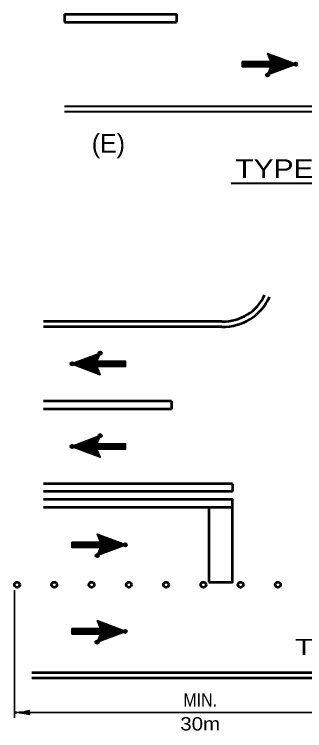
# Model space of a CAD drawing. Extents: x -96 to 617, y -65 to 388.
# Drawn here: x 326.3 to 380.8, y 106.9 to 241.5 of the extents above; entities that cross this region are included whole.
import ezdxf
from ezdxf.enums import TextEntityAlignment as Align

# ---------------------------------------------------------------- set-up
doc = ezdxf.new("R2010")
doc.units = 0
doc.header["$PDMODE"] = 32
doc.header["$PDSIZE"] = 0.5
doc.layers.add('1', color=7, linetype='Continuous', lineweight=53)

msp = doc.modelspace()

# ---------------------------------------------------------------- linework, layer by layer
at = {"layer": '1'}
for p, q in [((335.757, 241.515), (335.757, 240.015)), ((335.757, 241.515), (356.757, 241.515)), ((356.757, 241.515), (356.757, 240.015)), ((335.757, 240.015), (356.757, 240.015)), ((365.315, 183.817), (331.815, 183.817)), ((365.315, 182.817), (331.815, 182.817)), ((355.815, 168.817), (331.815, 168.817)), ((355.815, 168.817), (355.815, 167.317)), ((355.815, 167.317), (331.815, 167.317)), ((367.315, 153.317), (331.815, 153.317)), ((367.315, 153.317), (367.315, 151.817)), ((367.315, 151.817), (331.815, 151.817)), ((367.315, 148.817), (331.815, 148.817)), ((362.815, 148.817), (362.815, 134.817)), ((329.565, 117.817), (472.565, 117.817)), ((329.565, 116.817), (472.565, 116.817))]:
    msp.add_line(p, q, dxfattribs=at)
at = {"layer": '1', "lineweight": 35}
for p, q in [((373.891, 234.063), (376.827, 231.228)), ((373.992, 233.861), (376.726, 231.127)), ((374.093, 234.063), (376.928, 231.228)), ((374.093, 233.658), (376.625, 231.127)), ((374.195, 233.355), (376.523, 231.127)), ((374.296, 233.962), (377.03, 231.33)), ((374.296, 233.152), (376.422, 231.026)), ((374.397, 232.95), (376.321, 231.026)), ((374.498, 233.962), (377.131, 231.33)), ((374.802, 233.861), (377.232, 231.33)), ((375.005, 233.76), (377.333, 231.431)), ((375.207, 233.658), (377.435, 231.431)), ((375.41, 233.557), (377.536, 231.532)), ((375.713, 233.456), (377.637, 231.532)), ((375.916, 233.355), (377.738, 231.532)), ((376.118, 233.355), (377.84, 231.633)), ((376.422, 233.253), (377.941, 231.633)), ((376.625, 233.152), (378.042, 231.735)), ((376.827, 233.051), (378.143, 231.735)), ((377.03, 232.95), (378.245, 231.735)), ((369.132, 232.646), (374.498, 232.646)), ((369.132, 232.545), (370.043, 231.633)), ((369.132, 232.443), (369.942, 231.633)), ((369.132, 232.342), (369.841, 231.633)), ((369.132, 232.14), (369.638, 231.633)), ((369.132, 232.038), (369.537, 231.633)), ((369.132, 231.836), (369.335, 231.633)), ((369.132, 231.735), (369.233, 231.633)), ((369.233, 232.646), (370.246, 231.633)), ((369.335, 232.646), (370.347, 231.633)), ((369.537, 232.646), (370.55, 231.633)), ((369.638, 232.646), (370.651, 231.633)), ((369.841, 232.646), (370.853, 231.633)), ((369.942, 232.646), (370.955, 231.633)), ((370.043, 232.646), (371.056, 231.633)), ((370.246, 232.646), (371.258, 231.633)), ((370.347, 232.646), (371.36, 231.633)), ((370.55, 232.646), (371.562, 231.633)), ((370.651, 232.646), (371.663, 231.633)), ((370.752, 232.646), (371.765, 231.633)), ((370.955, 232.646), (371.967, 231.633)), ((371.056, 232.646), (372.068, 231.633)), ((371.258, 232.646), (372.271, 231.633)), ((371.36, 232.646), (372.372, 231.633)), ((371.562, 232.646), (372.575, 231.633)), ((371.663, 232.646), (372.676, 231.633)), ((371.765, 232.646), (372.777, 231.633)), ((371.967, 232.646), (372.98, 231.633)), ((372.068, 232.646), (373.081, 231.633)), ((372.271, 232.646), (373.283, 231.633)), ((372.372, 232.646), (373.385, 231.633)), ((372.473, 232.646), (373.486, 231.633)), ((372.676, 232.646), (373.688, 231.633)), ((372.777, 232.646), (373.79, 231.633)), ((372.98, 232.646), (373.992, 231.633)), ((373.081, 232.646), (374.093, 231.633)), ((373.182, 232.646), (374.195, 231.633)), ((373.385, 232.646), (374.397, 231.633)), ((373.486, 232.646), (375.41, 230.722)), ((373.688, 232.646), (375.612, 230.722)), ((373.79, 232.646), (375.713, 230.823)), ((373.992, 232.646), (375.815, 230.823)), ((374.093, 232.646), (375.916, 230.823)), ((374.195, 232.646), (376.017, 230.925)), ((374.397, 232.646), (376.118, 230.925)), ((374.498, 232.646), (376.22, 231.026)), ((377.333, 232.848), (378.346, 231.836)), ((377.536, 232.747), (378.447, 231.836)), ((377.738, 232.747), (378.548, 231.836)), ((377.941, 232.646), (378.65, 231.937)), ((378.245, 232.545), (378.751, 231.937)), ((378.447, 232.443), (378.852, 232.038)), ((378.65, 232.342), (378.953, 232.038)), ((378.852, 232.241), (379.055, 232.038)), ((373.891, 230.216), (373.992, 230.115)), ((373.992, 230.418), (374.195, 230.216)), ((373.992, 230.317), (374.093, 230.216)), ((374.093, 230.722), (374.498, 230.317)), ((374.093, 230.621), (374.397, 230.317)), ((374.093, 230.52), (374.296, 230.317)), ((374.195, 230.925), (374.701, 230.418)), ((374.195, 230.823), (374.6, 230.418)), ((374.296, 231.228), (375.005, 230.52)), ((374.296, 231.127), (374.903, 230.52)), ((374.296, 231.026), (374.802, 230.52)), ((374.397, 231.431), (375.207, 230.621)), ((374.397, 231.33), (375.106, 230.621)), ((374.498, 231.532), (375.308, 230.621)), ((342.339, 177.539), (342.136, 177.741)), ((342.339, 177.64), (342.238, 177.741)), ((342.44, 177.741), (342.339, 177.842)), ((340.415, 174.602), (338.592, 176.425)), ((340.618, 174.501), (338.694, 176.425)), ((340.921, 174.4), (338.795, 176.425)), ((341.124, 174.299), (338.896, 176.526)), ((341.326, 174.197), (338.998, 176.526)), ((341.529, 174.096), (339.099, 176.627)), ((341.832, 173.995), (339.2, 176.627)), ((342.035, 173.995), (339.301, 176.627)), ((342.238, 173.894), (339.402, 176.729)), ((342.44, 173.894), (339.504, 176.729)), ((342.339, 174.096), (339.605, 176.83)), ((342.238, 174.299), (339.706, 176.83)), ((342.136, 174.602), (339.808, 176.83)), ((342.035, 174.805), (339.909, 176.931)), ((341.934, 175.007), (340.01, 176.931)), ((341.832, 175.311), (340.111, 176.931)), ((341.934, 175.311), (340.212, 177.032)), ((342.136, 175.311), (340.314, 177.032)), ((342.238, 175.311), (340.415, 177.134)), ((342.339, 175.311), (340.516, 177.134)), ((342.541, 175.311), (340.618, 177.134)), ((342.642, 175.311), (340.719, 177.235)), ((342.845, 175.311), (340.921, 177.235)), ((341.832, 176.425), (341.022, 177.336)), ((341.934, 176.526), (341.124, 177.336)), ((341.934, 176.627), (341.225, 177.336)), ((342.035, 176.729), (341.326, 177.437)), ((342.035, 176.83), (341.428, 177.437)), ((342.035, 176.931), (341.529, 177.437)), ((342.136, 177.032), (341.63, 177.539)), ((342.136, 177.134), (341.731, 177.539)), ((342.238, 177.235), (341.832, 177.64)), ((342.238, 177.336), (341.934, 177.64)), ((342.238, 177.437), (342.035, 177.64)), ((337.479, 175.716), (337.276, 175.919)), ((337.681, 175.615), (337.377, 175.919)), ((337.884, 175.514), (337.479, 175.919)), ((338.086, 175.412), (337.58, 176.02)), ((338.39, 175.311), (337.681, 176.02)), ((338.592, 175.21), (337.782, 176.121)), ((338.795, 175.21), (337.884, 176.121)), ((338.998, 175.109), (337.985, 176.121)), ((339.301, 175.007), (338.086, 176.222)), ((339.504, 174.906), (338.188, 176.222)), ((339.706, 174.805), (338.289, 176.222)), ((339.909, 174.704), (338.39, 176.324)), ((340.212, 174.602), (338.491, 176.324)), ((347.199, 175.311), (341.832, 175.311)), ((342.946, 175.311), (341.934, 176.324)), ((343.149, 175.311), (342.136, 176.324)), ((343.25, 175.311), (342.238, 176.324)), ((343.351, 175.311), (342.339, 176.324)), ((343.554, 175.311), (342.541, 176.324)), ((343.655, 175.311), (342.642, 176.324)), ((343.858, 175.311), (342.845, 176.324)), ((343.959, 175.311), (342.946, 176.324)), ((344.06, 175.311), (343.048, 176.324)), ((344.262, 175.311), (343.25, 176.324)), ((344.364, 175.311), (343.351, 176.324)), ((344.566, 175.311), (343.554, 176.324)), ((344.667, 175.311), (343.655, 176.324)), ((344.769, 175.311), (343.756, 176.324)), ((344.971, 175.311), (343.959, 176.324)), ((345.072, 175.311), (344.06, 176.324)), ((345.275, 175.311), (344.262, 176.324)), ((345.376, 175.311), (344.364, 176.324)), ((345.579, 175.311), (344.566, 176.324)), ((345.68, 175.311), (344.667, 176.324)), ((345.781, 175.311), (344.769, 176.324)), ((345.984, 175.311), (344.971, 176.324)), ((346.085, 175.311), (345.072, 176.324)), ((346.287, 175.311), (345.275, 176.324)), ((346.389, 175.311), (345.376, 176.324)), ((346.49, 175.311), (345.477, 176.324)), ((346.692, 175.311), (345.68, 176.324)), ((346.794, 175.311), (345.781, 176.324)), ((346.996, 175.311), (345.984, 176.324)), ((347.097, 175.311), (346.085, 176.324)), ((347.199, 175.412), (346.287, 176.324)), ((347.199, 175.514), (346.389, 176.324)), ((347.199, 175.615), (346.49, 176.324)), ((347.199, 175.817), (346.692, 176.324)), ((347.199, 175.919), (346.794, 176.324)), ((347.199, 176.121), (346.996, 176.324)), ((347.199, 176.222), (347.097, 176.324)), ((342.238, 159.811), (340.415, 161.634)), ((342.339, 159.811), (340.516, 161.634)), ((342.541, 159.811), (340.618, 161.634)), ((342.642, 159.811), (340.719, 161.735)), ((342.845, 159.811), (340.921, 161.735)), ((341.832, 160.925), (341.022, 161.836)), ((341.934, 161.026), (341.124, 161.836)), ((341.934, 161.127), (341.225, 161.836)), ((342.035, 161.229), (341.326, 161.937)), ((342.035, 161.33), (341.428, 161.937)), ((342.035, 161.431), (341.529, 161.937)), ((342.136, 161.532), (341.63, 162.039)), ((342.136, 161.634), (341.731, 162.039)), ((342.238, 161.735), (341.832, 162.14)), ((342.238, 161.836), (341.934, 162.14)), ((342.238, 161.937), (342.035, 162.14)), ((342.339, 162.039), (342.136, 162.241)), ((342.339, 162.14), (342.238, 162.241)), ((342.44, 162.241), (342.339, 162.342)), ((337.479, 160.216), (337.276, 160.419)), ((337.681, 160.115), (337.377, 160.419)), ((337.884, 160.014), (337.479, 160.419)), ((338.086, 159.912), (337.58, 160.52)), ((338.39, 159.811), (337.681, 160.52)), ((338.592, 159.71), (337.782, 160.621)), ((338.795, 159.71), (337.884, 160.621)), ((338.998, 159.609), (337.985, 160.621)), ((339.301, 159.507), (338.086, 160.722)), ((339.504, 159.406), (338.188, 160.722)), ((339.706, 159.305), (338.289, 160.722)), ((339.909, 159.204), (338.39, 160.824)), ((340.212, 159.102), (338.491, 160.824)), ((340.415, 159.102), (338.592, 160.925)), ((340.618, 159.001), (338.694, 160.925)), ((340.921, 158.9), (338.795, 160.925)), ((341.124, 158.799), (338.896, 161.026)), ((341.326, 158.697), (338.998, 161.026)), ((341.529, 158.596), (339.099, 161.127)), ((341.832, 158.495), (339.2, 161.127)), ((342.035, 158.495), (339.301, 161.127)), ((342.238, 158.394), (339.402, 161.229)), ((342.44, 158.394), (339.504, 161.229)), ((342.339, 158.596), (339.605, 161.33)), ((342.238, 158.799), (339.706, 161.33)), ((342.136, 159.102), (339.808, 161.33)), ((342.035, 159.305), (339.909, 161.431)), ((341.934, 159.507), (340.01, 161.431)), ((341.832, 159.811), (340.111, 161.431)), ((341.934, 159.811), (340.212, 161.532)), ((342.136, 159.811), (340.314, 161.532)), ((342.946, 159.811), (341.934, 160.824)), ((343.149, 159.811), (342.136, 160.824)), ((343.25, 159.811), (342.238, 160.824)), ((343.351, 159.811), (342.339, 160.824)), ((343.554, 159.811), (342.541, 160.824)), ((343.655, 159.811), (342.642, 160.824)), ((343.858, 159.811), (342.845, 160.824)), ((343.959, 159.811), (342.946, 160.824)), ((344.06, 159.811), (343.048, 160.824)), ((344.262, 159.811), (343.25, 160.824)), ((344.364, 159.811), (343.351, 160.824)), ((344.566, 159.811), (343.554, 160.824)), ((344.667, 159.811), (343.655, 160.824)), ((344.769, 159.811), (343.756, 160.824)), ((344.971, 159.811), (343.959, 160.824)), ((345.072, 159.811), (344.06, 160.824)), ((345.275, 159.811), (344.262, 160.824)), ((345.376, 159.811), (344.364, 160.824)), ((345.579, 159.811), (344.566, 160.824)), ((345.68, 159.811), (344.667, 160.824)), ((345.781, 159.811), (344.769, 160.824)), ((345.984, 159.811), (344.971, 160.824)), ((346.085, 159.811), (345.072, 160.824)), ((346.287, 159.811), (345.275, 160.824)), ((346.389, 159.811), (345.376, 160.824)), ((346.49, 159.811), (345.477, 160.824)), ((346.692, 159.811), (345.68, 160.824)), ((346.794, 159.811), (345.781, 160.824)), ((346.996, 159.811), (345.984, 160.824)), ((347.097, 159.811), (346.085, 160.824)), ((347.199, 159.912), (346.287, 160.824)), ((347.199, 160.014), (346.389, 160.824)), ((347.199, 160.115), (346.49, 160.824)), ((347.199, 160.317), (346.692, 160.824)), ((347.199, 160.419), (346.794, 160.824)), ((347.199, 160.621), (346.996, 160.824)), ((347.199, 160.722), (347.097, 160.824)), ((347.199, 159.811), (341.832, 159.811)), ((341.879, 143.741), (344.816, 140.906)), ((341.981, 143.539), (344.714, 140.805)), ((342.082, 143.741), (344.917, 140.906)), ((342.082, 143.336), (344.613, 140.805)), ((342.183, 143.032), (344.512, 140.805)), ((342.284, 143.64), (345.018, 141.007)), ((342.284, 142.83), (344.411, 140.704)), ((342.487, 143.64), (345.119, 141.007)), ((342.791, 143.539), (345.221, 141.007)), ((342.993, 143.437), (345.322, 141.109)), ((343.196, 143.336), (345.423, 141.109)), ((343.398, 143.235), (345.524, 141.21)), ((343.702, 143.134), (345.626, 141.21)), ((343.904, 143.032), (345.727, 141.21)), ((344.107, 143.032), (345.828, 141.311)), ((344.411, 142.931), (345.929, 141.311)), ((344.613, 142.83), (346.031, 141.412)), ((344.816, 142.729), (346.132, 141.412)), ((337.121, 142.324), (342.487, 142.324)), ((337.121, 142.222), (338.032, 141.311)), ((337.121, 142.121), (337.931, 141.311)), ((337.121, 142.02), (337.829, 141.311)), ((337.121, 141.817), (337.627, 141.311)), ((337.121, 141.716), (337.526, 141.311)), ((337.121, 141.514), (337.323, 141.311)), ((337.121, 141.412), (337.222, 141.311)), ((337.222, 142.324), (338.234, 141.311)), ((337.323, 142.324), (338.336, 141.311)), ((337.526, 142.324), (338.538, 141.311)), ((337.627, 142.324), (338.639, 141.311)), ((337.829, 142.324), (338.842, 141.311)), ((337.931, 142.324), (338.943, 141.311)), ((338.032, 142.324), (339.044, 141.311)), ((338.234, 142.324), (339.247, 141.311)), ((338.336, 142.324), (339.348, 141.311)), ((338.538, 142.324), (339.551, 141.311)), ((338.639, 142.324), (339.652, 141.311)), ((338.741, 142.324), (339.753, 141.311)), ((338.943, 142.324), (339.956, 141.311)), ((339.044, 142.324), (340.057, 141.311)), ((339.247, 142.324), (340.259, 141.311)), ((339.348, 142.324), (340.361, 141.311)), ((339.551, 142.324), (340.563, 141.311)), ((339.652, 142.324), (340.664, 141.311)), ((339.753, 142.324), (340.766, 141.311)), ((339.956, 142.324), (340.968, 141.311)), ((340.057, 142.324), (341.069, 141.311)), ((340.259, 142.324), (341.272, 141.311)), ((340.361, 142.324), (341.373, 141.311)), ((340.462, 142.324), (341.474, 141.311)), ((340.664, 142.324), (341.677, 141.311)), ((340.766, 142.324), (341.778, 141.311)), ((340.968, 142.324), (341.981, 141.311)), ((341.069, 142.324), (342.082, 141.311)), ((341.171, 142.324), (342.183, 141.311)), ((341.373, 142.324), (342.386, 141.311)), ((341.474, 142.324), (343.398, 140.4)), ((341.677, 142.324), (343.601, 140.4)), ((341.778, 142.324), (343.702, 140.501)), ((341.981, 142.324), (343.803, 140.501)), ((342.082, 142.324), (343.904, 140.501)), ((342.183, 142.324), (344.006, 140.602)), ((342.386, 142.627), (344.309, 140.704)), ((342.386, 142.324), (344.107, 140.602)), ((342.487, 142.324), (344.208, 140.704)), ((345.018, 142.627), (346.233, 141.412)), ((345.322, 142.526), (346.334, 141.514)), ((345.524, 142.425), (346.436, 141.514)), ((345.727, 142.425), (346.537, 141.514)), ((345.929, 142.324), (346.638, 141.615)), ((346.233, 142.222), (346.739, 141.615)), ((346.436, 142.121), (346.841, 141.716)), ((346.638, 142.02), (346.942, 141.716)), ((346.841, 141.919), (347.043, 141.716)), ((341.981, 140.096), (342.183, 139.894)), ((342.082, 140.4), (342.487, 139.995)), ((342.082, 140.299), (342.386, 139.995)), ((342.082, 140.197), (342.284, 139.995)), ((342.183, 140.602), (342.689, 140.096)), ((342.183, 140.501), (342.588, 140.096)), ((342.284, 140.906), (342.993, 140.197)), ((342.284, 140.805), (342.892, 140.197)), ((342.284, 140.704), (342.791, 140.197)), ((342.386, 141.109), (343.196, 140.299)), ((342.386, 141.007), (343.094, 140.299)), ((342.487, 141.21), (343.297, 140.299)), ((341.879, 139.894), (341.981, 139.792)), ((341.981, 139.995), (342.082, 139.894)), ((326.315, 133.317), (326.315, 109.317)), ((341.879, 127.491), (344.816, 124.656)), ((341.981, 127.289), (344.714, 124.555)), ((342.082, 127.491), (344.917, 124.656)), ((342.082, 127.086), (344.613, 124.555)), ((342.183, 126.782), (344.512, 124.555)), ((342.284, 127.39), (345.018, 124.757)), ((342.284, 126.58), (344.411, 124.454)), ((342.487, 127.39), (345.119, 124.757)), ((342.791, 127.289), (345.221, 124.757)), ((342.993, 127.187), (345.322, 124.859)), ((343.196, 127.086), (345.423, 124.859)), ((343.398, 126.985), (345.524, 124.96)), ((343.702, 126.884), (345.626, 124.96)), ((343.904, 126.782), (345.727, 124.96)), ((344.107, 126.782), (345.828, 125.061)), ((344.411, 126.681), (345.929, 125.061)), ((344.613, 126.58), (346.031, 125.162)), ((337.121, 126.074), (342.487, 126.074)), ((337.121, 125.972), (338.032, 125.061)), ((337.121, 125.871), (337.931, 125.061)), ((337.121, 125.77), (337.829, 125.061)), ((337.121, 125.567), (337.627, 125.061)), ((337.121, 125.466), (337.526, 125.061)), ((337.121, 125.264), (337.323, 125.061)), ((337.222, 126.074), (338.234, 125.061)), ((337.323, 126.074), (338.336, 125.061)), ((337.526, 126.074), (338.538, 125.061)), ((337.627, 126.074), (338.639, 125.061)), ((337.829, 126.074), (338.842, 125.061)), ((337.931, 126.074), (338.943, 125.061)), ((338.032, 126.074), (339.044, 125.061)), ((338.234, 126.074), (339.247, 125.061)), ((338.336, 126.074), (339.348, 125.061)), ((338.538, 126.074), (339.551, 125.061)), ((338.639, 126.074), (339.652, 125.061)), ((338.741, 126.074), (339.753, 125.061)), ((338.943, 126.074), (339.956, 125.061)), ((339.044, 126.074), (340.057, 125.061)), ((339.247, 126.074), (340.259, 125.061)), ((339.348, 126.074), (340.361, 125.061)), ((339.551, 126.074), (340.563, 125.061)), ((339.652, 126.074), (340.664, 125.061)), ((339.753, 126.074), (340.766, 125.061)), ((339.956, 126.074), (340.968, 125.061)), ((340.057, 126.074), (341.069, 125.061)), ((340.259, 126.074), (341.272, 125.061)), ((340.361, 126.074), (341.373, 125.061)), ((340.462, 126.074), (341.474, 125.061)), ((340.664, 126.074), (341.677, 125.061)), ((340.766, 126.074), (341.778, 125.061)), ((340.968, 126.074), (341.981, 125.061)), ((341.069, 126.074), (342.082, 125.061)), ((341.171, 126.074), (342.183, 125.061)), ((341.373, 126.074), (342.386, 125.061)), ((341.474, 126.074), (343.398, 124.15)), ((341.677, 126.074), (343.601, 124.15)), ((341.778, 126.074), (343.702, 124.251)), ((341.981, 126.074), (343.803, 124.251)), ((342.082, 126.074), (343.904, 124.251)), ((342.183, 126.074), (344.006, 124.352)), ((342.386, 126.377), (344.309, 124.454)), ((342.386, 126.074), (344.107, 124.352)), ((342.487, 126.074), (344.208, 124.454)), ((344.816, 126.479), (346.132, 125.162)), ((345.018, 126.377), (346.233, 125.162)), ((345.322, 126.276), (346.334, 125.264)), ((345.524, 126.175), (346.436, 125.264)), ((345.727, 126.175), (346.537, 125.264)), ((345.929, 126.074), (346.638, 125.365)), ((346.233, 125.972), (346.739, 125.365)), ((346.436, 125.871), (346.841, 125.466)), ((346.638, 125.77), (346.942, 125.466)), ((346.841, 125.669), (347.043, 125.466)), ((337.121, 125.162), (337.222, 125.061)), ((341.981, 123.846), (342.183, 123.644)), ((342.082, 124.15), (342.487, 123.745)), ((342.082, 124.049), (342.386, 123.745)), ((342.082, 123.947), (342.284, 123.745)), ((342.183, 124.352), (342.689, 123.846)), ((342.183, 124.251), (342.588, 123.846)), ((342.284, 124.656), (342.993, 123.947)), ((342.284, 124.555), (342.892, 123.947)), ((342.284, 124.454), (342.791, 123.947)), ((342.386, 124.859), (343.196, 124.049)), ((342.386, 124.757), (343.094, 124.049)), ((342.487, 124.96), (343.297, 124.049)), ((341.879, 123.644), (341.981, 123.542)), ((341.981, 123.745), (342.082, 123.644))]:
    msp.add_line(p, q, dxfattribs=at)
at = {"layer": '1', "lineweight": 40}
for p, q in [((335.757, 224.265), (446.257, 224.265)), ((335.757, 223.265), (446.257, 223.265)), ((367.007, 209.768), (424.245, 209.768))]:
    msp.add_line(p, q, dxfattribs=at)
at = {"layer": '1', "lineweight": 35}
for points in [[(379.257, 232.14), (373.891, 230.115), (374.498, 231.633), (369.132, 231.633), (369.132, 232.646), (374.498, 232.646), (373.891, 234.165)], [(337.074, 175.817), (342.44, 177.842), (341.832, 176.324), (347.199, 176.324), (347.199, 175.311), (341.832, 175.311), (342.44, 173.792)], [(337.074, 160.317), (342.44, 162.342), (341.832, 160.824), (347.199, 160.824), (347.199, 159.811), (341.832, 159.811), (342.44, 158.292)], [(347.246, 141.817), (341.879, 139.792), (342.487, 141.311), (337.121, 141.311), (337.121, 142.324), (342.487, 142.324), (341.879, 143.842)], [(347.246, 125.567), (341.879, 123.542), (342.487, 125.061), (337.121, 125.061), (337.121, 126.074), (342.487, 126.074), (341.879, 127.592)]]:
    msp.add_lwpolyline(points, close=True, dxfattribs=at)
for points in [[(374.498, 231.633), (369.132, 231.633), (369.132, 232.646)], [(341.832, 176.324), (347.199, 176.324), (347.199, 175.311)], [(341.832, 160.824), (347.199, 160.824), (347.199, 159.811)], [(342.487, 141.311), (337.121, 141.311), (337.121, 142.324)], [(342.487, 125.061), (337.121, 125.061), (337.121, 126.074)], [(326.315, 110.317), (401.065, 110.317), (474.315, 110.317)]]:
    msp.add_lwpolyline(points, dxfattribs=at)
at = {"layer": '1'}
msp.add_lwpolyline([(362.815, 134.817), (367.315, 134.817), (367.315, 150.317), (331.815, 150.317)], dxfattribs=at)
for centre in [(326.815, 134.317), (333.815, 134.317), (340.815, 134.317), (347.815, 134.317), (354.815, 134.317), (361.815, 134.317), (368.815, 134.317), (375.815, 134.317)]:
    msp.add_circle(centre, 0.5, dxfattribs=at)
for radius in [8.411, 9.411]:
    msp.add_arc((365.624, 192.223), radius, 267.89429, 336.11648, dxfattribs=at)
at = {"layer": '1', "lineweight": 40}
for centre, major_axis, ratio, start_param, end_param in [((327.406, 110.594), (-1.786, -0.156), 0.122415, 0.8963533, 3.1415927), ((327.406, 110.594), (-1.786, -0.156), 0.122415, 0.8963533, 3.1415927), ((327.435, 110.106), (-1.756, 0.176), 0.07063, 3.1407148, 5.41811), ((327.435, 110.106), (-1.756, 0.176), 0.07063, 3.1407148, 5.41811)]:
    msp.add_ellipse(centre, major_axis=major_axis, ratio=ratio, start_param=start_param, end_param=end_param, dxfattribs=at)
at = {"layer": '1'}
for p in [(379.156, 232.14), (373.891, 230.115), (342.44, 177.842), (337.175, 175.817), (342.44, 162.342), (337.175, 160.317), (347.144, 141.817), (341.879, 139.792), (347.144, 125.567), (341.879, 123.542)]:
    msp.add_point(p, dxfattribs=at)

# ---------------------------------------------------------------- texts
msp.add_text('(E)', height=3.5, dxfattribs=at).set_placement((343.969, 215.538), align=Align.CENTER)
for s, height, width, p in [('TYPE C-4 MARKERS', 3.5, 1.2, (395.137, 210.768)), ('THRU         LANE', 3, 1.4, (401.183, 121.119)), ('MIN.', 2.5, 0.9, (361.219, 111.436)), ('30m', 2.5, 1.15, (361.219, 106.936))]:
    msp.add_text(s, height=height, dxfattribs=dict(at, width=width)).set_placement(p, align=Align.CENTER)

doc.saveas('drawing.dxf')
